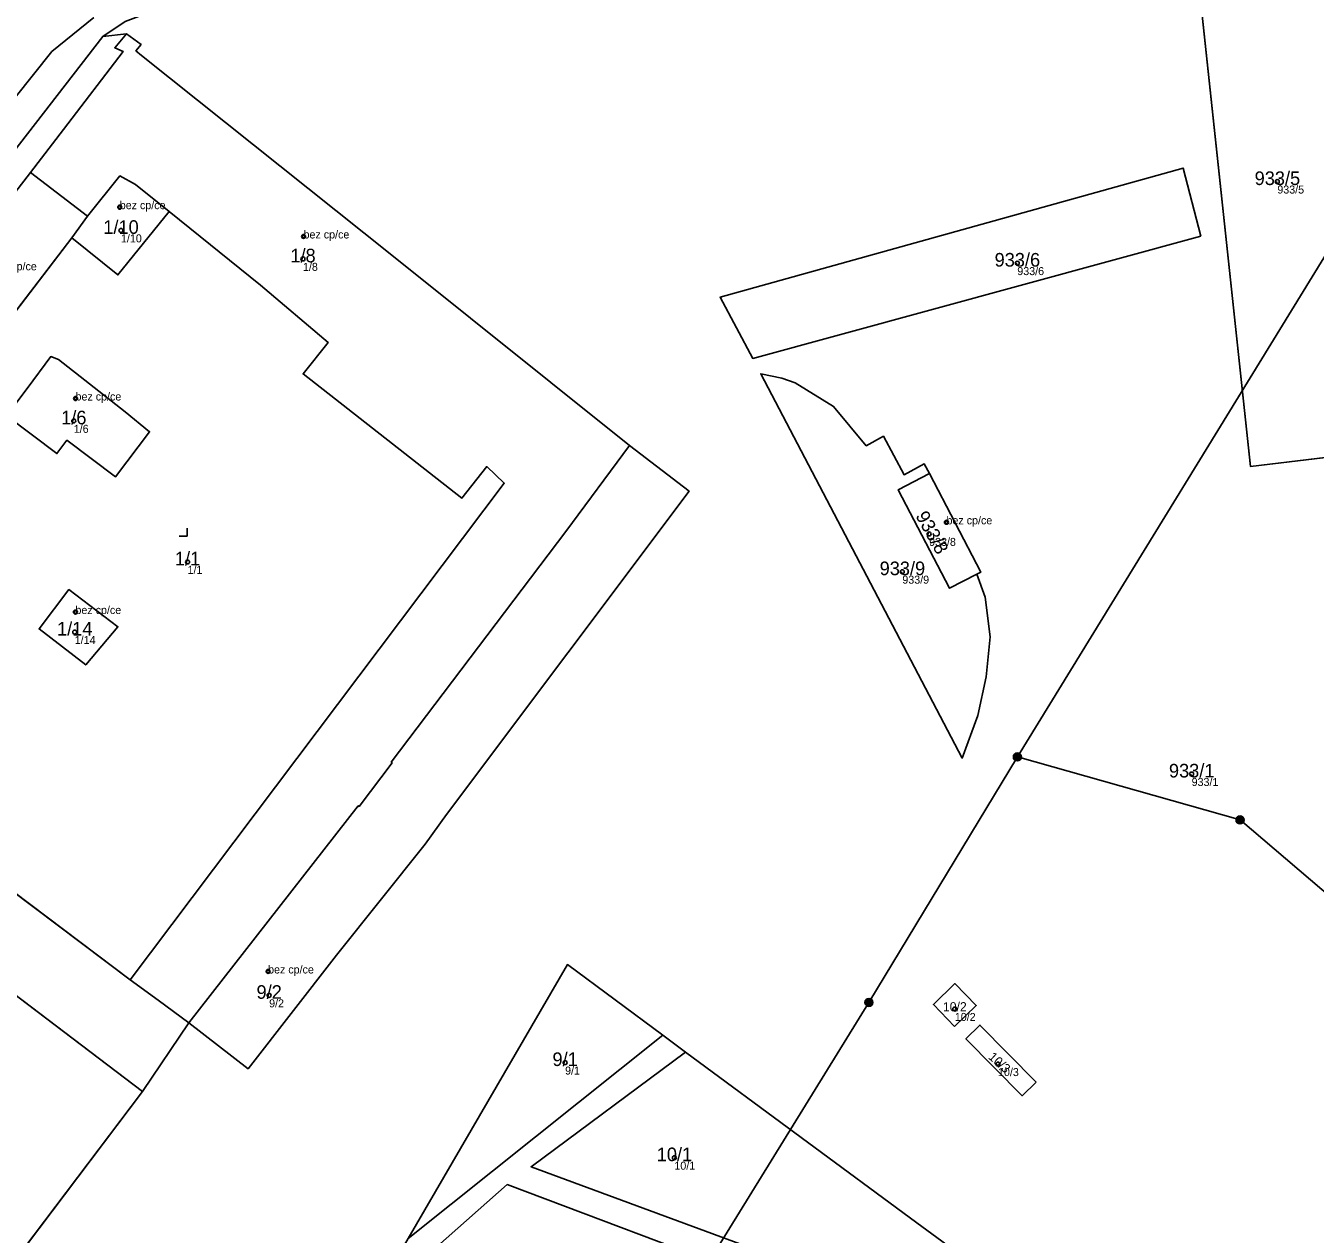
# Model space of a CAD drawing. Extents: x -603967 to -594699, y -1179315 to -1165625.
# Drawn here: x -597406.8 to -597245.6, y -1172370 to -1172219 of the extents above; entities that cross this region are included whole.
import ezdxf

# ---------------------------------------------------------------- set-up
doc = ezdxf.new("R2010")
doc.units = 0
for name, color, linetype in [('Definiční body', 7, 'Continuous'), ('Hranice parcel', 7, 'Continuous'), ('Parcelní čísla', 7, 'Continuous'), ('Polygon budovy', 7, 'Continuous'), ('Polygon parcely', 7, 'Continuous'), ('Poz předměty', 7, 'Continuous'), ('Vnitřní kresba', 7, 'Continuous'), ('Značky budov', 7, 'Continuous'), ('Značky kultur', 7, 'Continuous')]:
    doc.layers.add(name, color=color, linetype=linetype)

msp = doc.modelspace()

# ---------------------------------------------------------------- linework, layer by layer
at = {"layer": 'Definiční body'}
for centre in [(-597250.36, -1172238.50994), (-597395.04, -1172241.69994), (-597394.89, -1172244.60994), (-597372.07, -1172245.35994), (-597372.14, -1172248.16994), (-597282.86, -1172248.69994), (-597400.57, -1172265.60994), (-597400.79, -1172268.40994), (-597291.71, -1172281.07994), (-597293.88, -1172282.53994), (-597386.57, -1172286.02994), (-597297.23, -1172287.25994), (-597400.58, -1172292.28994), (-597400.67, -1172294.79994), (-597261.07, -1172312.53994), (-597376.5, -1172337.20994), (-597376.37, -1172340.19994), (-597290.67, -1172341.89994), (-597339.38, -1172348.59994), (-597285.27, -1172348.78994), (-597325.72, -1172360.48994)]:
    msp.add_circle(centre, 0.25, dxfattribs=at)
at = {"layer": 'Hranice parcel'}
for p, q in [((-597253.73, -1172274.09), (-597260.88, -1172207.18)), ((-597394.18, -1172220.06), (-597397.14, -1172220.36)), ((-597406.2, -1172237.37), (-597399.08, -1172242.83)), ((-597399.08, -1172242.83), (-597401.01, -1172245.53)), ((-597401.01, -1172245.53), (-597415.08, -1172263.86)), ((-597323.89, -1172277.19), (-597331.31, -1172271.49)), ((-597240.82, -1172272.56), (-597253.73, -1172274.09)), ((-597436.01, -1172306.41), (-597393.75, -1172338.24)), ((-597392.19, -1172352.22), (-597438.64, -1172316.97)), ((-597393.75, -1172338.24), (-597390.26, -1172340.79)), ((-597390.26, -1172340.79), (-597386.39, -1172343.63)), ((-597386.39, -1172343.63), (-597392.19, -1172352.22)), ((-597358.99, -1172370.57), (-597327.17, -1172345.18)), ((-597324.33, -1172347.29), (-597327.17, -1172345.18)), ((-597410.06, -1172375.83), (-597392.19, -1172352.22))]:
    msp.add_line(p, q, dxfattribs=at)
for points in [[(-597389.04, -1172216.48), (-597394.37, -1172218.5), (-597397.14, -1172220.36)], [(-597394.18, -1172220.06), (-597395.66, -1172221.77), (-597394.62, -1172222.24), (-597402.07, -1172231.99), (-597406.2, -1172237.37)], [(-597392.33, -1172222.74), (-597393.02, -1172222.16), (-597392.37, -1172221.39), (-597394.18, -1172220.06)], [(-597397.14, -1172220.36), (-597427.14, -1172259.05), (-597454.04, -1172292.81)], [(-597331.31, -1172271.49), (-597361.05, -1172247.68), (-597392.33, -1172222.74)], [(-597424.28, -1172260.92), (-597408.14, -1172239.9), (-597406.2, -1172237.37)], [(-597399.08, -1172242.83), (-597395.02, -1172237.79), (-597393.09, -1172238.88), (-597388.88, -1172242.25)], [(-597259.94, -1172245.31), (-597315.93, -1172260.6), (-597320.01, -1172252.96), (-597262.13, -1172236.82), (-597259.94, -1172245.31)], [(-597388.88, -1172242.25), (-597395.28, -1172250.16), (-597401.01, -1172245.53)], [(-597393.75, -1172338.24), (-597346.99, -1172276.17), (-597349.17, -1172274.12), (-597352.28, -1172278.06), (-597372.12, -1172262.53), (-597368.99, -1172258.62), (-597377.43, -1172251.43), (-597388.88, -1172242.25)], [(-597406.63, -1172264.37), (-597403.67, -1172260.38), (-597402.7, -1172260.75), (-597394.37, -1172267.29), (-597391.32, -1172269.77)], [(-597287.91, -1172287.55), (-597286.89, -1172290.45), (-597286.27, -1172295.38), (-597286.74, -1172300.41), (-597287.78, -1172305.22), (-597289.74, -1172310.54), (-597314.92, -1172262.52), (-597312.31, -1172263.05), (-597310.63, -1172263.65), (-597305.82, -1172266.59), (-597301.74, -1172271.52), (-597299.59, -1172270.33), (-597297.01, -1172275.14), (-597294.49, -1172273.79), (-597293.85, -1172274.99)], [(-597391.32, -1172269.77), (-597395.59, -1172275.41), (-597401.64, -1172270.82), (-597402.89, -1172272.49), (-597409.15, -1172267.77), (-597407.89, -1172266.06), (-597406.63, -1172264.37)], [(-597386.39, -1172343.63), (-597365.24, -1172316.49), (-597365.12, -1172316.58), (-597360.99, -1172311.14), (-597361.11, -1172311.04), (-597339.27, -1172282.23), (-597331.31, -1172271.49)], [(-597293.85, -1172274.99), (-597297.75, -1172277.03), (-597291.33, -1172289.32), (-597287.91, -1172287.55)], [(-597293.85, -1172274.99), (-597287.4, -1172287.29), (-597287.91, -1172287.55)], [(-597356.86, -1172321.31), (-597354.19, -1172317.61), (-597323.89, -1172277.19)], [(-597395.28, -1172294.13), (-597399.29, -1172298.91), (-597405.13, -1172294.41), (-597401.4, -1172289.49), (-597395.28, -1172294.13)], [(-597386.39, -1172343.63), (-597379, -1172349.37), (-597367.96, -1172335.16), (-597356.86, -1172321.31)], [(-597327.17, -1172345.18), (-597339.09, -1172336.35), (-597358.99, -1172370.57)], [(-597290.69, -1172344.07), (-597293.35, -1172341.35), (-597290.67, -1172338.73), (-597288, -1172341.45), (-597290.69, -1172344.07)], [(-597280.5, -1172351.05), (-597282.24, -1172352.73), (-597289.28, -1172345.61), (-597287.54, -1172343.9), (-597280.5, -1172351.05)], [(-597324.33, -1172347.29), (-597343.63, -1172361.61), (-597265.82, -1172390.33)], [(-597265.82, -1172390.33), (-597295.4, -1172368.6), (-597324.33, -1172347.29)], [(-597364.05, -1172379.26), (-597346.63, -1172363.83), (-597254.5, -1172398.58)]]:
    msp.add_lwpolyline(points, dxfattribs=at)
at = {"layer": 'Polygon budovy'}
for points in [[(-597393.75, -1172338.24), (-597390.26, -1172340.79), (-597386.39, -1172343.63), (-597365.24, -1172316.49), (-597365.12, -1172316.58), (-597360.99, -1172311.14), (-597361.11, -1172311.04), (-597339.27, -1172282.23), (-597331.31, -1172271.49), (-597361.05, -1172247.68), (-597392.33, -1172222.74), (-597393.02, -1172222.16), (-597392.37, -1172221.39), (-597394.18, -1172220.06), (-597395.66, -1172221.77), (-597394.62, -1172222.24), (-597402.07, -1172231.99), (-597406.2, -1172237.37), (-597399.08, -1172242.83), (-597395.02, -1172237.79), (-597393.09, -1172238.88), (-597388.88, -1172242.25), (-597377.43, -1172251.43), (-597368.99, -1172258.62), (-597372.12, -1172262.53), (-597352.28, -1172278.06), (-597349.17, -1172274.12), (-597346.99, -1172276.17)], [(-597415.08, -1172263.86), (-597401.01, -1172245.53), (-597399.08, -1172242.83), (-597406.2, -1172237.37), (-597408.14, -1172239.9), (-597424.28, -1172260.92), (-597417.09, -1172266.5)], [(-597401.01, -1172245.53), (-597395.28, -1172250.16), (-597388.88, -1172242.25), (-597393.09, -1172238.88), (-597395.02, -1172237.79), (-597399.08, -1172242.83)], [(-597409.15, -1172267.77), (-597402.89, -1172272.49), (-597401.64, -1172270.82), (-597395.59, -1172275.41), (-597391.32, -1172269.77), (-597394.37, -1172267.29), (-597402.7, -1172260.75), (-597403.67, -1172260.38), (-597406.63, -1172264.37), (-597407.89, -1172266.06)], [(-597331.31, -1172271.49), (-597339.27, -1172282.23), (-597361.11, -1172311.04), (-597360.99, -1172311.14), (-597365.12, -1172316.58), (-597365.24, -1172316.49), (-597386.39, -1172343.63), (-597379, -1172349.37), (-597367.96, -1172335.16), (-597356.86, -1172321.31), (-597354.19, -1172317.61), (-597323.89, -1172277.19)], [(-597293.85, -1172274.99), (-597297.75, -1172277.03), (-597291.33, -1172289.32), (-597287.91, -1172287.55), (-597287.4, -1172287.29)], [(-597405.13, -1172294.41), (-597399.29, -1172298.91), (-597395.28, -1172294.13), (-597401.4, -1172289.49)], [(-597438.64, -1172316.97), (-597392.19, -1172352.22), (-597386.39, -1172343.63), (-597390.26, -1172340.79), (-597393.75, -1172338.24), (-597436.01, -1172306.41), (-597441.83, -1172314.55)]]:
    msp.add_lwpolyline(points, close=True, dxfattribs=at)
at = {"layer": 'Polygon parcely'}
for points in [[(-597591.42, -1172351.56), (-597523.81, -1172359.42), (-597520.82, -1172360.39), (-597519.02, -1172360.12), (-597508.72, -1172358.64), (-597503.65, -1172355.71), (-597502.19, -1172353.11), (-597498.46, -1172346.48), (-597454.04, -1172292.81), (-597427.14, -1172259.05), (-597397.14, -1172220.36), (-597394.37, -1172218.5), (-597389.04, -1172216.48), (-597385.49, -1172215.44), (-597284.94, -1172206.98), (-597176.28, -1172194.43), (-597149.06, -1172188.37), (-597103.95, -1172176.52), (-597093.36, -1172173.46), (-597048.28, -1172157.97), (-597028.02, -1172148.91), (-597019.27, -1172145.73)], [(-597240.82, -1172272.56), (-597253.73, -1172274.09), (-597260.88, -1172207.18), (-597260.97, -1172206.33), (-597341.02, -1172212.91), (-597389.04, -1172216.48), (-597394.37, -1172218.5), (-597397.14, -1172220.36), (-597394.18, -1172220.06), (-597392.37, -1172221.39), (-597393.02, -1172222.16), (-597392.33, -1172222.74), (-597361.05, -1172247.68), (-597331.31, -1172271.49), (-597323.89, -1172277.19), (-597354.19, -1172317.61), (-597356.86, -1172321.31), (-597367.96, -1172335.16), (-597379, -1172349.37), (-597386.39, -1172343.63), (-597392.19, -1172352.22), (-597410.06, -1172375.83)], [(-597408.14, -1172239.9), (-597406.2, -1172237.37), (-597402.07, -1172231.99), (-597394.62, -1172222.24), (-597395.66, -1172221.77), (-597394.18, -1172220.06), (-597397.14, -1172220.36), (-597427.14, -1172259.05)], [(-597358.99, -1172370.57), (-597339.09, -1172336.35), (-597327.17, -1172345.18), (-597324.33, -1172347.29), (-597295.4, -1172368.6), (-597265.82, -1172390.33)]]:
    msp.add_lwpolyline(points, dxfattribs=at)
for points in [[(-597240.89, -1172236.82), (-597242.04, -1172223.18), (-597243.85, -1172204.92), (-597260.97, -1172206.33), (-597260.88, -1172207.18), (-597253.73, -1172274.09), (-597240.82, -1172272.56), (-597237.84, -1172272.31), (-597238.71, -1172261.86)], [(-597365.24, -1172316.49), (-597365.12, -1172316.58), (-597360.99, -1172311.14), (-597361.11, -1172311.04), (-597339.27, -1172282.23), (-597331.31, -1172271.49), (-597361.05, -1172247.68), (-597392.33, -1172222.74), (-597393.02, -1172222.16), (-597392.37, -1172221.39), (-597394.18, -1172220.06), (-597395.66, -1172221.77), (-597394.62, -1172222.24), (-597402.07, -1172231.99), (-597406.2, -1172237.37), (-597399.08, -1172242.83), (-597395.02, -1172237.79), (-597393.09, -1172238.88), (-597388.88, -1172242.25), (-597377.43, -1172251.43), (-597368.99, -1172258.62), (-597372.12, -1172262.53), (-597352.28, -1172278.06), (-597349.17, -1172274.12), (-597346.99, -1172276.17), (-597393.75, -1172338.24), (-597390.26, -1172340.79), (-597386.39, -1172343.63)], [(-597415.08, -1172263.86), (-597401.01, -1172245.53), (-597399.08, -1172242.83), (-597406.2, -1172237.37), (-597408.14, -1172239.9), (-597424.28, -1172260.92), (-597417.09, -1172266.5)], [(-597399.08, -1172242.83), (-597401.01, -1172245.53), (-597395.28, -1172250.16), (-597388.88, -1172242.25), (-597393.09, -1172238.88), (-597395.02, -1172237.79)], [(-597259.94, -1172245.31), (-597262.13, -1172236.82), (-597320.01, -1172252.96), (-597315.93, -1172260.6)], [(-597259.94, -1172245.31), (-597315.93, -1172260.6), (-597320.01, -1172252.96), (-597262.13, -1172236.82)], [(-597368.99, -1172258.62), (-597377.43, -1172251.43), (-597388.88, -1172242.25), (-597395.28, -1172250.16), (-597401.01, -1172245.53), (-597415.08, -1172263.86), (-597417.09, -1172266.5), (-597424.28, -1172260.92), (-597428.55, -1172266.49), (-597423.8, -1172270), (-597420.8, -1172272.34), (-597425.55, -1172278.62), (-597428.45, -1172276.58), (-597443.12, -1172295.33), (-597433.34, -1172303), (-597436.01, -1172306.41), (-597393.75, -1172338.24), (-597346.99, -1172276.17), (-597349.17, -1172274.12), (-597352.28, -1172278.06), (-597372.12, -1172262.53)], [(-597391.32, -1172269.77), (-597395.59, -1172275.41), (-597401.64, -1172270.82), (-597402.89, -1172272.49), (-597409.15, -1172267.77), (-597407.89, -1172266.06), (-597406.63, -1172264.37), (-597403.67, -1172260.38), (-597402.7, -1172260.75), (-597394.37, -1172267.29)], [(-597391.32, -1172269.77), (-597394.37, -1172267.29), (-597402.7, -1172260.75), (-597403.67, -1172260.38), (-597406.63, -1172264.37), (-597407.89, -1172266.06), (-597409.15, -1172267.77), (-597402.89, -1172272.49), (-597401.64, -1172270.82), (-597395.59, -1172275.41)], [(-597293.85, -1172274.99), (-597294.49, -1172273.79), (-597297.01, -1172275.14), (-597299.59, -1172270.33), (-597301.74, -1172271.52), (-597305.82, -1172266.59), (-597310.63, -1172263.65), (-597312.31, -1172263.05), (-597314.92, -1172262.52), (-597289.74, -1172310.54), (-597287.78, -1172305.22), (-597286.74, -1172300.41), (-597286.27, -1172295.38), (-597286.89, -1172290.45), (-597287.91, -1172287.55), (-597291.33, -1172289.32), (-597297.75, -1172277.03)], [(-597287.91, -1172287.55), (-597286.89, -1172290.45), (-597286.27, -1172295.38), (-597286.74, -1172300.41), (-597287.78, -1172305.22), (-597289.74, -1172310.54), (-597314.92, -1172262.52), (-597312.31, -1172263.05), (-597310.63, -1172263.65), (-597305.82, -1172266.59), (-597301.74, -1172271.52), (-597299.59, -1172270.33), (-597297.01, -1172275.14), (-597294.49, -1172273.79), (-597293.85, -1172274.99), (-597287.4, -1172287.29)], [(-597323.89, -1172277.19), (-597331.31, -1172271.49), (-597339.27, -1172282.23), (-597361.11, -1172311.04), (-597360.99, -1172311.14), (-597365.12, -1172316.58), (-597365.24, -1172316.49), (-597386.39, -1172343.63), (-597379, -1172349.37), (-597367.96, -1172335.16), (-597356.86, -1172321.31), (-597354.19, -1172317.61)], [(-597287.91, -1172287.55), (-597287.4, -1172287.29), (-597293.85, -1172274.99), (-597297.75, -1172277.03), (-597291.33, -1172289.32)], [(-597395.28, -1172294.13), (-597399.29, -1172298.91), (-597405.13, -1172294.41), (-597401.4, -1172289.49)], [(-597395.28, -1172294.13), (-597401.4, -1172289.49), (-597405.13, -1172294.41), (-597399.29, -1172298.91)], [(-597393.75, -1172338.24), (-597436.01, -1172306.41), (-597441.83, -1172314.55), (-597438.64, -1172316.97), (-597392.19, -1172352.22), (-597386.39, -1172343.63), (-597390.26, -1172340.79)], [(-597452.05, -1172341.15), (-597456.27, -1172348.76), (-597438.51, -1172353.31), (-597437.2, -1172347.76), (-597429.27, -1172349.76), (-597432.41, -1172361.37), (-597447.94, -1172357.37), (-597449, -1172362.21), (-597433.93, -1172367.48), (-597410.06, -1172375.83), (-597392.19, -1172352.22), (-597438.64, -1172316.97)], [(-597339.09, -1172336.35), (-597358.99, -1172370.57), (-597327.17, -1172345.18)], [(-597290.69, -1172344.07), (-597288, -1172341.45), (-597290.67, -1172338.73), (-597293.35, -1172341.35)], [(-597290.69, -1172344.07), (-597293.35, -1172341.35), (-597290.67, -1172338.73), (-597288, -1172341.45)], [(-597280.5, -1172351.05), (-597287.54, -1172343.9), (-597289.28, -1172345.61), (-597282.24, -1172352.73)], [(-597280.5, -1172351.05), (-597282.24, -1172352.73), (-597289.28, -1172345.61), (-597287.54, -1172343.9)], [(-597364.05, -1172379.26), (-597346.63, -1172363.83), (-597254.5, -1172398.58), (-597265.82, -1172390.33), (-597343.63, -1172361.61), (-597324.33, -1172347.29), (-597327.17, -1172345.18), (-597358.99, -1172370.57)], [(-597295.4, -1172368.6), (-597324.33, -1172347.29), (-597343.63, -1172361.61), (-597265.82, -1172390.33)], [(-597254.5, -1172398.58), (-597346.63, -1172363.83), (-597364.05, -1172379.26), (-597370.04, -1172389.55), (-597225.66, -1172519.43), (-597230.58, -1172397.86)]]:
    msp.add_lwpolyline(points, close=True, dxfattribs=at)
at = {"layer": 'Poz předměty'}
for p, q in [((-597282.85, -1172310.4), (-597220.36, -1172208.57)), ((-597282.85, -1172310.4), (-597301.41, -1172341.08)), ((-597282.85, -1172310.4), (-597255.02, -1172318.27)), ((-597225.18, -1172343.69), (-597255.02, -1172318.27)), ((-597301.41, -1172341.08), (-597337.64, -1172399.75))]:
    msp.add_line(p, q, dxfattribs=at)
for centre, radius in [((-597282.85343, -1172310.39988), 0.5), ((-597282.85343, -1172310.39988), 0.4), ((-597282.85343, -1172310.39988), 0.3), ((-597282.85343, -1172310.39988), 0.2), ((-597282.85343, -1172310.39988), 0.1), ((-597255.02343, -1172318.26988), 0.5), ((-597255.02343, -1172318.26988), 0.4), ((-597255.02343, -1172318.26988), 0.3), ((-597255.02343, -1172318.26988), 0.2), ((-597255.02343, -1172318.26988), 0.1), ((-597301.41343, -1172341.07988), 0.5), ((-597301.41343, -1172341.07988), 0.4), ((-597301.41343, -1172341.07988), 0.3), ((-597301.41343, -1172341.07988), 0.2), ((-597301.41343, -1172341.07988), 0.1)]:
    msp.add_circle(centre, radius, dxfattribs=at)
at = {"layer": 'Vnitřní kresba'}
for p in [(-597398.28, -1172218.01), (-597431.02, -1172256.53)]:
    msp.add_line(p, (-597403.53, -1172222.26), dxfattribs=at)
at = {"layer": 'Značky budov'}
for centre in [(-597395.0468, -1172241.69916), (-597372.0768, -1172245.35916), (-597400.5768, -1172265.60916), (-597291.7168, -1172281.07916), (-597400.5868, -1172292.28916), (-597376.5068, -1172337.20916)]:
    msp.add_circle(centre, 0.175, dxfattribs=at)
at = {"layer": 'Značky kultur'}
for p, q in [((-597387.631, -1172282.83), (-597386.63, -1172282.83)), ((-597386.63, -1172282.83), (-597386.63, -1172281.83))]:
    msp.add_line(p, q, dxfattribs=at)

# ---------------------------------------------------------------- texts
at = {"layer": 'Definiční body'}
for s, p in [('933/5', (-597250.36, -1172239.999)), ('bez cp/ce', (-597395.04, -1172241.95)), ('1/10', (-597394.89, -1172246.099)), ('bez cp/ce', (-597372.07, -1172245.61)), ('bez cp/ce', (-597411.13, -1172249.59)), ('1/8', (-597372.14, -1172249.659)), ('933/6', (-597282.86, -1172250.189)), ('bez cp/ce', (-597400.57, -1172265.86)), ('1/6', (-597400.79, -1172269.899)), ('bez cp/ce', (-597291.71, -1172281.33)), ('933/8', (-597293.88, -1172284.029)), ('1/1', (-597386.57, -1172287.519)), ('933/9', (-597297.23, -1172288.749)), ('bez cp/ce', (-597400.58, -1172292.54)), ('1/14', (-597400.67, -1172296.289)), ('933/1', (-597261.07, -1172314.029)), ('bez cp/ce', (-597376.5, -1172337.46)), ('9/2', (-597376.37, -1172341.689)), ('10/2', (-597290.67, -1172343.389)), ('9/1', (-597339.38, -1172350.089)), ('10/3', (-597285.27, -1172350.279)), ('10/1', (-597325.72, -1172361.979))]:
    msp.add_text(s, height=0.999996, dxfattribs=at).set_placement(p)
at = {"layer": 'Parcelní čísla'}
for s, height, p in [('933/5', 1.699998, (-597253.196, -1172238.935)), ('1/10', 1.699998, (-597397.095, -1172245.035)), ('1/8', 1.699998, (-597373.715, -1172248.595)), ('933/6', 1.699998, (-597285.696, -1172249.125)), ('1/6', 1.699998, (-597402.365, -1172268.835)), ('1/1', 1.699998, (-597388.145, -1172286.455)), ('933/9', 1.699998, (-597300.066, -1172287.685)), ('1/14', 1.699998, (-597402.875, -1172295.225)), ('933/1', 1.699998, (-597263.906, -1172312.965)), ('9/2', 1.699998, (-597377.945, -1172340.625)), ('10/2', 1.14, (-597292.149, -1172342.185)), ('9/1', 1.699998, (-597340.955, -1172349.025)), ('10/1', 1.699998, (-597327.925, -1172360.915))]:
    msp.add_text(s, height=height, dxfattribs=at).set_placement(p)
for s, height, rotation, p in [('933/8', 1.699998, 298.9999972, (-597295.626, -1172280.265)), ('10/3', 1.14, 318, (-597286.559, -1172348.012))]:
    msp.add_text(s, height=height, rotation=rotation, dxfattribs=at).set_placement(p)

doc.saveas('drawing.dxf')
